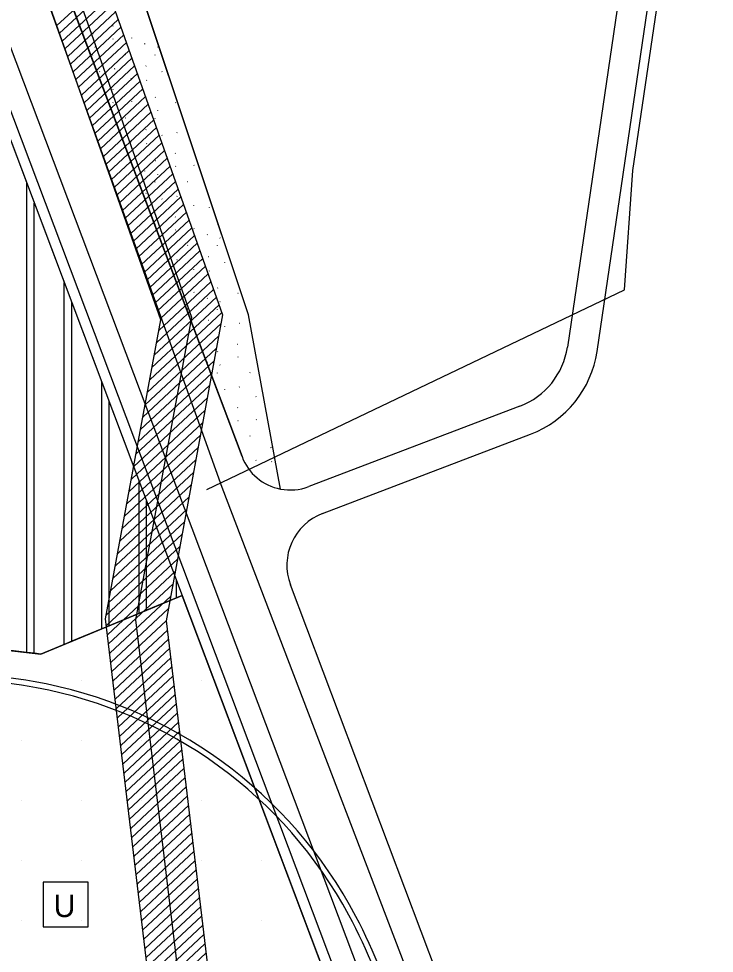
# Model space of a CAD drawing. Extents: x 409341 to 428634, y 4447481 to 4463281.
# Drawn here: x 419872 to 420336, y 4459096 to 4459720 of the extents above; entities that cross this region are included whole.
import ezdxf

# ---------------------------------------------------------------- set-up
doc = ezdxf.new("R2010")
doc.units = 0
for name, color, linetype in [('ADA', 7, 'Continuous'), ('ADAKENARI', 7, 'Continuous'), ('Default', 7, 'Continuous'), ('KALDIRIM', 7, 'Continuous'), ('LJ_SEMBOL', 7, 'Continuous'), ('OSB', 7, 'Continuous'), ('PL_AYA_PARK_DINLENME', 7, 'Continuous'), ('PL_K_ASKERI_ALAN', 7, 'Continuous'), ('PL_SAY_YUKSEK_UNIVER', 7, 'Continuous'), ('RAYLI_TOPLU_TAŞIMA_HATTI', 7, 'Continuous'), ('SN_ILCE', 7, 'Continuous'), ('TA_ENH_154', 7, 'Continuous'), ('TA_ENH_KORUMA', 7, 'Continuous'), ('TA_ENH_TARAMA', 7, 'Continuous'), ('TR_ASKERIALAN', 7, 'Continuous'), ('TR_PARKALANI', 7, 'Continuous'), ('TR_YUKSEKEGITIM', 7, 'Continuous')]:
    doc.layers.add(name, color=color, linetype=linetype)

# ---------------------------------------------------------------- blocks, each defined once
blk = doc.blocks.new('POINT_DISPLAY')
at = {"layer": 'Default'}
blk.add_line((0, 0), (0, 0), dxfattribs=at)

msp = doc.modelspace()

# ---------------------------------------------------------------- linework, layer by layer
at = {"layer": 'ADA'}
for p, q in [((420025.24, 4459521.91), (419866.54, 4459998.46)), ((420046.61, 4459405.73), (420025.24, 4459521.91)), ((419886.72, 4459295.63), (419981.1, 4459334.68)), ((419718.68, 4459315.02), (419886.72, 4459295.63))]:
    msp.add_line(p, q, dxfattribs=at)
at = {"layer": 'ADAKENARI'}
for p, q in [((420298.87, 4459913.63), (420237.99, 4459500.49)), ((420257.77, 4459497.58), (420318.34, 4459908.53)), ((420020.95, 4459427.38), (419842.52, 4459900.56)), ((419847.21, 4459689.72), (419981.1, 4459334.68)), ((420206.33, 4459461.06), (420065.43, 4459407.36)), ((420074.75, 4459389.5), (420213.45, 4459442.37)), ((420322.63, 4458627.34), (420053.24, 4459341.74)), ((419981.1, 4459334.68), (420163.9, 4458849.89))]:
    msp.add_line(p, q, dxfattribs=at)
for centre, radius, start, end in [((420188.52, 4459507.78), 50, 290.86422, 351.61675), ((420188.52, 4459507.78), 70, 290.86422, 351.61675), ((420053.17, 4459439.53), 34.43, 200.66043, 259.02219), ((420053.17, 4459439.53), 34.43, 259.02219, 290.86422), ((420087.96, 4459354.83), 37.1, 110.86422, 200.66043)]:
    msp.add_arc(centre, radius, start, end, dxfattribs=at)
at = {"layer": 'KALDIRIM'}
for p, q in [((420196.04, 4458827.01), (419860.78, 4459716.11)), ((420196.04, 4458827.01), (419860.78, 4459716.11)), ((420170.33, 4458852.66), (419849.91, 4459702.42)), ((420171.87, 4458848.59), (419849.91, 4459702.42)), ((420170.33, 4458852.66), (419849.91, 4459702.42)), ((420171.87, 4458848.59), (419849.91, 4459702.42))]:
    msp.add_line(p, q, dxfattribs=at)
at = {"layer": 'LJ_SEMBOL'}
msp.add_lwpolyline([(419888.27, 4459113.51), (419918.27, 4459113.51), (419918.27, 4459143.51), (419888.27, 4459143.51)], close=True, dxfattribs=at)
msp.add_lwpolyline([(419888.27, 4459113.51), (419918.27, 4459113.51), (419918.27, 4459143.51), (419888.27, 4459143.51)], close=True, dxfattribs=at)
at = {"layer": 'OSB'}
msp.add_lwpolyline([(420374, 4458402.25), (420333.73, 4458554.43), (420007.65, 4459406.75), (419828, 4459907.45), (419873.71, 4459964.63), (419861.99, 4460046.05), (419800.79, 4460096.52), (419788.07, 4460171.32), (419687.29, 4460251.24), (419645.19, 4460319.68), (419562.32, 4460570.29)], dxfattribs=at)
at = {"layer": 'PL_AYA_PARK_DINLENME'}
for points in [[(420046.61, 4459405.73), (420025.24, 4459521.91), (419866.54, 4459998.46), (419865.83, 4459985.61)], [(419842.52, 4459900.56), (420020.95, 4459427.38)]]:
    msp.add_lwpolyline(points, dxfattribs=at)
msp.add_arc((420053.17, 4459439.53), 34.43, 200.66043, 259.02219, dxfattribs=at)
at = {"layer": 'PL_K_ASKERI_ALAN'}
msp.add_lwpolyline([(419886.72, 4459295.63), (419718.68, 4459315.02), (419602.34, 4459605.86), (419847.21, 4459689.72), (419981.1, 4459334.68)], close=True, dxfattribs=at)
at = {"layer": 'PL_SAY_YUKSEK_UNIVER'}
msp.add_lwpolyline([(420163.9, 4458849.89), (419981.1, 4459334.68), (419977.34, 4459333.13), (419957.34, 4459324.85), (419952.34, 4459322.78), (419932.34, 4459314.51), (419927.34, 4459312.44), (419907.34, 4459304.16), (419902.34, 4459302.09), (419886.72, 4459295.63), (419882.34, 4459296.13), (419877.34, 4459296.71), (419857.34, 4459299.02)], dxfattribs=at)
at = {"layer": 'RAYLI_TOPLU_TAŞIMA_HATTI'}
for points in [[(419883.84, 4459273.13), (419878.91, 4459273.99), (419873.97, 4459274.78), (419869.03, 4459275.5), (419864.07, 4459276.15), (419859.1, 4459276.74), (419854.13, 4459277.27), (419849.16, 4459277.76), (419844.18, 4459278.2), (419839.19, 4459278.6), (419834.2, 4459278.96), (419829.22, 4459279.3), (419824.23, 4459279.62), (419819.24, 4459279.92), (419814.24, 4459280.21), (419809.25, 4459280.49)], [(419881.66, 4459277.29), (419876.73, 4459278.11), (419871.78, 4459278.85), (419866.83, 4459279.53), (419861.86, 4459280.13), (419856.89, 4459280.68), (419851.92, 4459281.18), (419846.94, 4459281.63), (419841.96, 4459282.03), (419836.97, 4459282.41), (419831.98, 4459282.75), (419826.99, 4459283.07), (419822, 4459283.37), (419817.01, 4459283.66), (419812.02, 4459283.94)], [(420122.21, 4459052.58), (420120.4, 4459057.24), (420118.6, 4459061.91), (420116.78, 4459066.56), (420114.95, 4459071.22), (420113.09, 4459075.86), (420111.21, 4459080.49), (420109.3, 4459085.11), (420107.36, 4459089.72), (420105.37, 4459094.31), (420103.33, 4459098.87), (420101.25, 4459103.42), (420099.11, 4459107.94), (420096.91, 4459112.43), (420094.64, 4459116.88), (420092.31, 4459121.3)], [(420124.64, 4459056.27), (420122.84, 4459060.93), (420121.03, 4459065.6), (420119.21, 4459070.25), (420117.38, 4459074.9), (420115.52, 4459079.55), (420113.64, 4459084.18), (420111.72, 4459088.8), (420109.76, 4459093.4), (420107.77, 4459097.98), (420105.72, 4459102.54), (420103.62, 4459107.08), (420101.46, 4459111.59), (420099.23, 4459116.07), (420096.94, 4459120.51)]]:
    msp.add_lwpolyline(points, dxfattribs=at)
for centre, radius, start, end in [((419829.86, 4458979.97), 301.8, 27.75363, 80.1173), ((419829.78, 4458979.87), 298.2, 28.31419, 79.55673)]:
    msp.add_arc(centre, radius, start, end, dxfattribs=at)
at = {"layer": 'SN_ILCE'}
msp.add_lwpolyline([(419997.51, 4459405.33), (420276.11, 4459538.7), (420281.55, 4459618.21), (420305.79, 4459782.43), (420319.14, 4459867.21), (420323.61, 4459925.59), (420326.96, 4459967.45), (420329.74, 4460074.97), (420331.95, 4460191.34), (420333.25, 4460234.41), (420383.34, 4460227.18), (420410.75, 4460229.16), (420433.9, 4460291.54), (420466.47, 4460352.6), (420553.34, 4460434.75), (420597.55, 4460463.65), (420660.19, 4460427.88), (420691.61, 4460515.94)], dxfattribs=at)
at = {"layer": 'TA_ENH_154'}
msp.add_lwpolyline([(420056.43, 4458431.11), (420019.86, 4458736.59), (419950.22, 4459318.44), (419987.39, 4459520.3), (419893.36, 4459786.57)], dxfattribs=at)
at = {"layer": 'TA_ENH_KORUMA'}
for p, q in [((419966.75, 4459518.67), (419875.52, 4459777.03)), ((419930, 4459319.08), (419966.75, 4459518.67)), ((420000, 4458734.21), (419930, 4459319.08))]:
    msp.add_line(p, q, dxfattribs=at)
msp.add_lwpolyline([(419911.21, 4459796.11), (420008.03, 4459521.93), (419970.44, 4459317.8), (420039.72, 4458738.96), (420097.57, 4458255.69), (420153.07, 4457792.04), (420153.62, 4457787.59)], dxfattribs=at)
at = {"layer": 'TA_ENH_TARAMA'}
for p, q in [((419897.43, 4459714.98), (419929.33, 4459744.78)), ((419899.25, 4459709.83), (419931.15, 4459739.64)), ((419901.07, 4459704.68), (419932.97, 4459734.49)), ((419902.88, 4459699.54), (419934.78, 4459729.35)), ((419904.7, 4459694.39), (419936.6, 4459724.2)), ((419906.52, 4459689.25), (419938.42, 4459719.06)), ((419908.34, 4459684.1), (419940.23, 4459713.91)), ((419910.15, 4459678.95), (419942.05, 4459708.76)), ((419911.97, 4459673.81), (419943.87, 4459703.62)), ((419913.79, 4459668.66), (419945.69, 4459698.47)), ((419915.6, 4459663.52), (419947.5, 4459693.33)), ((419917.42, 4459658.37), (419949.32, 4459688.18)), ((419919.24, 4459653.22), (419951.14, 4459683.03)), ((419921.06, 4459648.08), (419952.95, 4459677.89)), ((419922.87, 4459642.93), (419954.77, 4459672.74)), ((419924.69, 4459637.79), (419956.59, 4459667.6)), ((419926.51, 4459632.64), (419958.41, 4459662.45)), ((419928.33, 4459627.5), (419960.22, 4459657.3)), ((419930.14, 4459622.35), (419962.04, 4459652.16)), ((419931.96, 4459617.2), (419963.86, 4459647.01)), ((419933.78, 4459612.06), (419965.68, 4459641.87)), ((419935.59, 4459606.91), (419967.49, 4459636.72)), ((419937.41, 4459601.77), (419969.31, 4459631.57)), ((419939.23, 4459596.62), (419971.13, 4459626.43)), ((419941.05, 4459591.47), (419972.94, 4459621.28)), ((419942.86, 4459586.33), (419974.76, 4459616.14)), ((419944.68, 4459581.18), (419976.58, 4459610.99)), ((419946.5, 4459576.04), (419978.4, 4459605.85)), ((419948.31, 4459570.89), (419980.21, 4459600.7)), ((419950.13, 4459565.74), (419982.03, 4459595.55)), ((419951.95, 4459560.6), (419983.85, 4459590.41)), ((419953.77, 4459555.45), (419985.66, 4459585.26)), ((419955.58, 4459550.31), (419987.48, 4459580.12)), ((419957.4, 4459545.16), (419989.3, 4459574.97)), ((419959.22, 4459540.01), (419991.12, 4459569.82)), ((419961.04, 4459534.87), (419992.93, 4459564.68)), ((419962.85, 4459529.72), (419994.75, 4459559.53)), ((419964.67, 4459524.58), (419996.57, 4459554.39)), ((419966.49, 4459519.43), (419998.39, 4459549.24)), ((419965.46, 4459511.62), (420000.2, 4459544.09)), ((419963.93, 4459503.36), (420002.02, 4459538.95)), ((419962.41, 4459495.09), (420003.84, 4459533.8)), ((419959.37, 4459478.56), (420007.47, 4459523.51)), ((419960.89, 4459486.82), (420005.65, 4459528.66)), ((419957.84, 4459470.29), (420006.98, 4459516.2)), ((419956.32, 4459462.02), (420005.45, 4459507.94)), ((419954.8, 4459453.76), (420003.93, 4459499.67)), ((419953.28, 4459445.49), (420002.41, 4459491.4)), ((419951.75, 4459437.22), (420000.89, 4459483.14)), ((419950.23, 4459428.96), (419999.36, 4459474.87)), ((419948.71, 4459420.69), (419997.84, 4459466.6)), ((419947.19, 4459412.42), (419996.32, 4459458.34)), ((419945.66, 4459404.16), (419994.8, 4459450.07)), ((419944.14, 4459395.89), (419993.27, 4459441.8)), ((419942.62, 4459387.62), (419991.75, 4459433.54)), ((419941.1, 4459379.35), (419990.23, 4459425.27)), ((419939.57, 4459371.09), (419988.71, 4459417)), ((419938.05, 4459362.82), (419987.18, 4459408.74)), ((419936.53, 4459354.55), (419985.66, 4459400.47)), ((419935.01, 4459346.29), (419984.14, 4459392.2)), ((419933.48, 4459338.02), (419982.62, 4459383.93)), ((419931.96, 4459329.75), (419981.09, 4459375.67)), ((419930.44, 4459321.49), (419979.57, 4459367.4)), ((419930.52, 4459314.72), (419978.05, 4459359.13)), ((419931.25, 4459308.56), (419976.53, 4459350.87)), ((419931.99, 4459302.4), (419975, 4459342.6)), ((419932.73, 4459296.25), (419973.48, 4459334.33)), ((419933.46, 4459290.09), (419971.96, 4459326.07)), ((419934.2, 4459283.94), (419970.44, 4459317.8)), ((419934.94, 4459277.78), (419971.17, 4459311.65)), ((419935.68, 4459271.63), (419971.91, 4459305.49)), ((419936.41, 4459265.47), (419972.65, 4459299.33)), ((419937.15, 4459259.32), (419973.39, 4459293.18)), ((419937.89, 4459253.16), (419974.12, 4459287.02)), ((419938.62, 4459247), (419974.86, 4459280.87)), ((419939.36, 4459240.85), (419975.6, 4459274.71)), ((419940.1, 4459234.69), (419976.33, 4459268.56)), ((419940.83, 4459228.54), (419977.07, 4459262.4)), ((419941.57, 4459222.38), (419977.81, 4459256.25)), ((419942.31, 4459216.23), (419978.54, 4459250.09)), ((419943.04, 4459210.07), (419979.28, 4459243.93)), ((419943.78, 4459203.92), (419980.02, 4459237.78)), ((419944.52, 4459197.76), (419980.75, 4459231.62)), ((419945.25, 4459191.6), (419981.49, 4459225.47)), ((419945.99, 4459185.45), (419982.23, 4459219.31)), ((419946.73, 4459179.29), (419982.96, 4459213.16)), ((419947.46, 4459173.14), (419983.7, 4459207)), ((419948.2, 4459166.98), (419984.44, 4459200.85)), ((419948.94, 4459160.83), (419985.17, 4459194.69)), ((419949.67, 4459154.67), (419985.91, 4459188.53)), ((419950.41, 4459148.52), (419986.65, 4459182.38)), ((419951.15, 4459142.36), (419987.38, 4459176.22)), ((419951.88, 4459136.2), (419988.12, 4459170.07)), ((419952.62, 4459130.05), (419988.86, 4459163.91)), ((419953.36, 4459123.89), (419989.59, 4459157.76)), ((419954.09, 4459117.74), (419990.33, 4459151.6)), ((419954.83, 4459111.58), (419991.07, 4459145.44)), ((419955.57, 4459105.43), (419991.8, 4459139.29)), ((419956.31, 4459099.27), (419992.54, 4459133.13)), ((419957.04, 4459093.12), (419993.28, 4459126.98)), ((419957.78, 4459086.96), (419994.02, 4459120.82)), ((419958.52, 4459080.8), (419994.75, 4459114.67)), ((419959.25, 4459074.65), (419995.49, 4459108.51)), ((419959.99, 4459068.49), (419996.23, 4459102.36)), ((419960.73, 4459062.34), (419996.96, 4459096.2))]:
    msp.add_line(p, q, dxfattribs=at)
at = {"layer": 'TR_ASKERIALAN'}
for p, q in [((419877.34, 4459296.71), (419877.34, 4459609.83)), ((419882.34, 4459296.13), (419882.34, 4459596.57)), ((419902.34, 4459302.09), (419902.34, 4459543.53)), ((419907.34, 4459304.16), (419907.34, 4459530.27)), ((419927.34, 4459312.44), (419927.34, 4459477.23)), ((419932.34, 4459314.51), (419932.34, 4459463.97)), ((419952.34, 4459322.78), (419952.34, 4459410.93)), ((419957.34, 4459324.85), (419957.34, 4459397.67)), ((419977.34, 4459333.13), (419977.34, 4459344.63))]:
    msp.add_line(p, q, dxfattribs=at)
at = {"layer": 'TR_PARKALANI'}
for p, q in [((419934.7, 4459714.74), (419934.84, 4459714.52)), ((419921.59, 4459709.67), (419921.36, 4459709.55)), ((419935.11, 4459706.02), (419934.87, 4459705.91)), ((419947.15, 4459706.84), (419947.29, 4459706.62)), ((419922.85, 4459700.77), (419922.99, 4459700.55)), ((419956.15, 4459702.7), (419956.18, 4459702.95)), ((419964.51, 4459700.77), (419964.65, 4459700.55)), ((419921.32, 4459695.33), (419921.36, 4459695.58)), ((419943.15, 4459695.7), (419942.92, 4459695.58)), ((419962.98, 4459695.33), (419963.02, 4459695.58)), ((419936.02, 4459686.05), (419935.78, 4459685.94)), ((419956.97, 4459688.03), (419956.74, 4459687.91)), ((419925.89, 4459684.29), (419926.03, 4459684.07)), ((419946.88, 4459679.77), (419947.02, 4459679.55)), ((419967.55, 4459684.29), (419967.69, 4459684.07)), ((419957.32, 4459678.67), (419957.46, 4459678.45)), ((419934.7, 4459672.29), (419934.84, 4459672.07)), ((419963.25, 4459667.23), (419963.02, 4459667.11)), ((419935.11, 4459663.58), (419934.87, 4459663.47)), ((419947.15, 4459664.4), (419947.29, 4459664.18)), ((419956.15, 4459660.25), (419956.18, 4459660.51)), ((419976.77, 4459663.58), (419976.53, 4459663.47)), ((419964.51, 4459658.32), (419964.65, 4459658.1)), ((419943.15, 4459653.26), (419942.92, 4459653.14)), ((419962.98, 4459652.88), (419963.02, 4459653.14)), ((419956.97, 4459645.58), (419956.74, 4459645.47)), ((419967.55, 4459641.85), (419967.69, 4459641.63)), ((419977.68, 4459643.61), (419977.44, 4459643.5)), ((419946.88, 4459637.33), (419947.02, 4459637.11)), ((419957.32, 4459636.23), (419957.46, 4459636.01)), ((419976.36, 4459629.85), (419976.5, 4459629.63)), ((419963.25, 4459624.78), (419963.02, 4459624.67)), ((419956.15, 4459617.81), (419956.18, 4459618.06)), ((419976.77, 4459621.14), (419976.53, 4459621.02)), ((419988.81, 4459621.95), (419988.95, 4459621.73)), ((419962.98, 4459610.44), (419963.02, 4459610.7)), ((419964.51, 4459615.88), (419964.65, 4459615.66)), ((419984.81, 4459610.81), (419984.58, 4459610.7)), ((419956.97, 4459603.14), (419956.74, 4459603.03)), ((419967.55, 4459599.4), (419967.69, 4459599.18)), ((419977.68, 4459601.17), (419977.44, 4459601.05)), ((419988.54, 4459594.88), (419988.68, 4459594.67)), ((419998.98, 4459593.78), (419999.12, 4459593.56)), ((419976.36, 4459587.4), (419976.5, 4459587.19)), ((419963.25, 4459582.34), (419963.02, 4459582.22)), ((419988.81, 4459579.51), (419988.95, 4459579.29)), ((420004.91, 4459582.34), (420004.68, 4459582.22)), ((419976.77, 4459578.69), (419976.53, 4459578.58)), ((419997.81, 4459575.36), (419997.84, 4459575.62)), ((420006.17, 4459573.43), (420006.31, 4459573.22)), ((419984.81, 4459568.37), (419984.58, 4459568.25)), ((420004.64, 4459568), (420004.68, 4459568.25)), ((419998.63, 4459560.7), (419998.4, 4459560.58)), ((419977.68, 4459558.72), (419977.44, 4459558.61)), ((420009.21, 4459556.96), (420009.35, 4459556.74)), ((419988.54, 4459552.44), (419988.68, 4459552.22)), ((419998.98, 4459551.34), (419999.12, 4459551.12)), ((419988.81, 4459537.06), (419988.95, 4459536.85)), ((420004.91, 4459539.89), (420004.68, 4459539.78)), ((420018.43, 4459536.25), (420018.19, 4459536.13)), ((419997.81, 4459532.92), (419997.84, 4459533.18)), ((420006.17, 4459530.99), (420006.31, 4459530.77)), ((419984.81, 4459525.92), (419984.58, 4459525.81)), ((420004.64, 4459525.55), (420004.68, 4459525.81)), ((419998.63, 4459518.25), (419998.4, 4459518.14)), ((420009.21, 4459514.51), (420009.35, 4459514.29)), ((420019.34, 4459516.28), (420019.1, 4459516.16)), ((419998.98, 4459508.89), (419999.12, 4459508.68)), ((420018.02, 4459502.52), (420018.16, 4459502.3)), ((420004.91, 4459497.45), (420004.68, 4459497.33)), ((420018.43, 4459493.8), (420018.19, 4459493.69)), ((419997.81, 4459490.48), (419997.84, 4459490.73)), ((420006.17, 4459488.55), (420006.31, 4459488.33)), ((420004.64, 4459483.11), (420004.68, 4459483.36)), ((420026.48, 4459483.48), (420026.24, 4459483.36)), ((420019.34, 4459473.83), (420019.1, 4459473.72)), ((420009.21, 4459472.07), (420009.35, 4459471.85)), ((420030.2, 4459467.55), (420030.34, 4459467.33)), ((420018.02, 4459460.07), (420018.16, 4459459.85)), ((420018.43, 4459451.36), (420018.19, 4459451.25)), ((420030.47, 4459452.18), (420030.61, 4459451.96)), ((420026.48, 4459441.04), (420026.24, 4459440.92)), ((420040.29, 4459433.36), (420040.06, 4459433.25)), ((420030.2, 4459425.11), (420030.34, 4459424.89)), ((420040.64, 4459424.01), (420040.78, 4459423.79))]:
    msp.add_line(p, q, dxfattribs=at)

# ---------------------------------------------------------------- block references
at = {"layer": 'TR_YUKSEKEGITIM', "xscale": 0.1, "yscale": 0.10000000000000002}
for p in [(419953.69, 4459317.92), (419873.69, 4459277.92), (419913.69, 4459277.92), (419953.69, 4459277.92), (419993.69, 4459277.92), (419873.69, 4459237.92), (419913.69, 4459237.92), (419953.69, 4459237.92), (419993.69, 4459237.92), (419873.69, 4459197.92), (419913.69, 4459197.92), (419953.69, 4459197.92), (419993.69, 4459197.92), (419873.69, 4459157.92), (419913.69, 4459157.92), (419953.69, 4459157.92), (419993.69, 4459157.92), (420033.69, 4459157.92), (419873.69, 4459117.92), (419913.69, 4459117.92), (419953.69, 4459117.92), (419993.69, 4459117.92), (420033.69, 4459117.92)]:
    msp.add_blockref('POINT_DISPLAY', p, dxfattribs=at)

# ---------------------------------------------------------------- texts
at = {"layer": 'LJ_SEMBOL'}
msp.add_text('U', height=15, dxfattribs=at).set_placement((419895.34, 4459120.14))
msp.add_text('U', height=15, dxfattribs=at).set_placement((419895.34, 4459120.14))

doc.saveas('drawing.dxf')
